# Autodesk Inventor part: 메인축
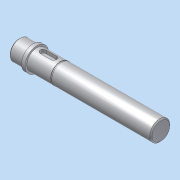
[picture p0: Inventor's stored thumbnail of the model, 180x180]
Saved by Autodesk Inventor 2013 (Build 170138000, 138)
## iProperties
Company: 한국ATC센터
Created: 2014-12
Part Number: 메인축
Document SubType Name: Modeling
Designer: KYOUNG IL JANG
Density: 1 g/cm^3
Mass: 27.2374 g
Surface Area: 71.2962 cm^2
Volume: 27.2374 cm^3
Material: 일반
Author: KYOUNG IL JANG
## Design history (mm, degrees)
sketch "스케치1"
  geometry: L1 (0, 0)-(120, 0); L2 (0, 0)-(0, 7.5); L3 (1, 8.5)-(12, 8.5); L4 (12, 8.5)-(12, 10); L5 (12, 10)-(15, 10); L6 (15, 10)-(15, 8.5); L7 (15, 8.5)-(119, 8.5); L8 (120, 0)-(120, 7.5); L9 (1, 8.5)-(0, 7.5); L10 (119, 8.5)-(120, 7.5); 2 further points
  constraints: 20 end point, 4 point on line, 3 parallel, 3 perpendicular, 1 collinear, 1 horizontal
  dimensions: "d0" = 12 distance of point (0, 8.5) L3.end; "d1" = 17 diameter of L3 L1; "d2" = 20 diameter of L5 L1; "d3" = 17 diameter of L7 L1; "d4" = 3 distance of L4.end L5.end; "d5" = 120 distance of L1.start L1.end; "d6" = 1 distance of L3.start point (0, 8.5); "d7" = 1 distance of L2.end point (0, 8.5) (= d6); "d8" = 1 distance of L7.end point (120, 8.5) (= d6); "d9" = 1 distance of L8.end point (120, 8.5) (= d8)
revolve "회전1" sketch "스케치1" stored, may be unused: angle "d10" = 90 deg
node "작업 평면1"
sketch "스케치2"
  geometry: L1 (-46.5, 2.5)-(-37.5, 2.5); L2 (-37.5, -2.5)-(-46.5, -2.5); L3 (-52, -10)-(-52, 10) reference; A1 r 2.5 centre (-37.5, 0) between (-37.5, -2.5) and (-37.5, 2.5); A2 r 2.5 centre (-46.5, 0) between (-46.5, 2.5) and (-46.5, -2.5); 1 further point
  constraints: 4 end point, 4 point on circle, 4 tangent, 2 centre point, 1 horizontal, 1 horizontal alignment, 1 parallel
  dimensions: "d11" = 5 distance between parallel lines of L2 L1; "d12" = 3 distance edge to line of A2 L3; "d13" = 14 dimension on A1 A2
extrude "돌출1" cut sketch "스케치2" distance "d14" = 3; taper "d15" = 0 deg
sketch "스케치3"
  geometry: L1 (15, 8.5)-(119, 8.5) reference; L2 (35, 8.5)-(36.15, 8.5); L3 (36.15, 8.5)-(36.15, 8.1); L4 (36.15, 8.1)-(35, 8.1); L5 (35, 8.1)-(35, 8.5); L6 (15, -10)-(15, 10) reference; L7 (-23.8, 0)-(142.8, 0) reference; 1 further point
  constraints: 8 end point, 2 parallel, 1 horizontal, 1 perpendicular, 1 point on line
  dimensions: "d16" = 1.15 distance of L3.end L4.end; "d17" = 20 distance between parallel lines of L5 L6; "d18" = 8.1 distance from line of L4 point (0, 0)
revolve "회전2" sketch "스케치3" stored, may be unused: angle "d19" = 90 deg
node "솔리드1"
